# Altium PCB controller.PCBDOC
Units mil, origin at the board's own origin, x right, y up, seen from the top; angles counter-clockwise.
Board outline 3870 x 2950 mil, 2 copper layers (Top Layer, Bottom Layer); 33 components, 42 nets, 131 pads, 36 vias.
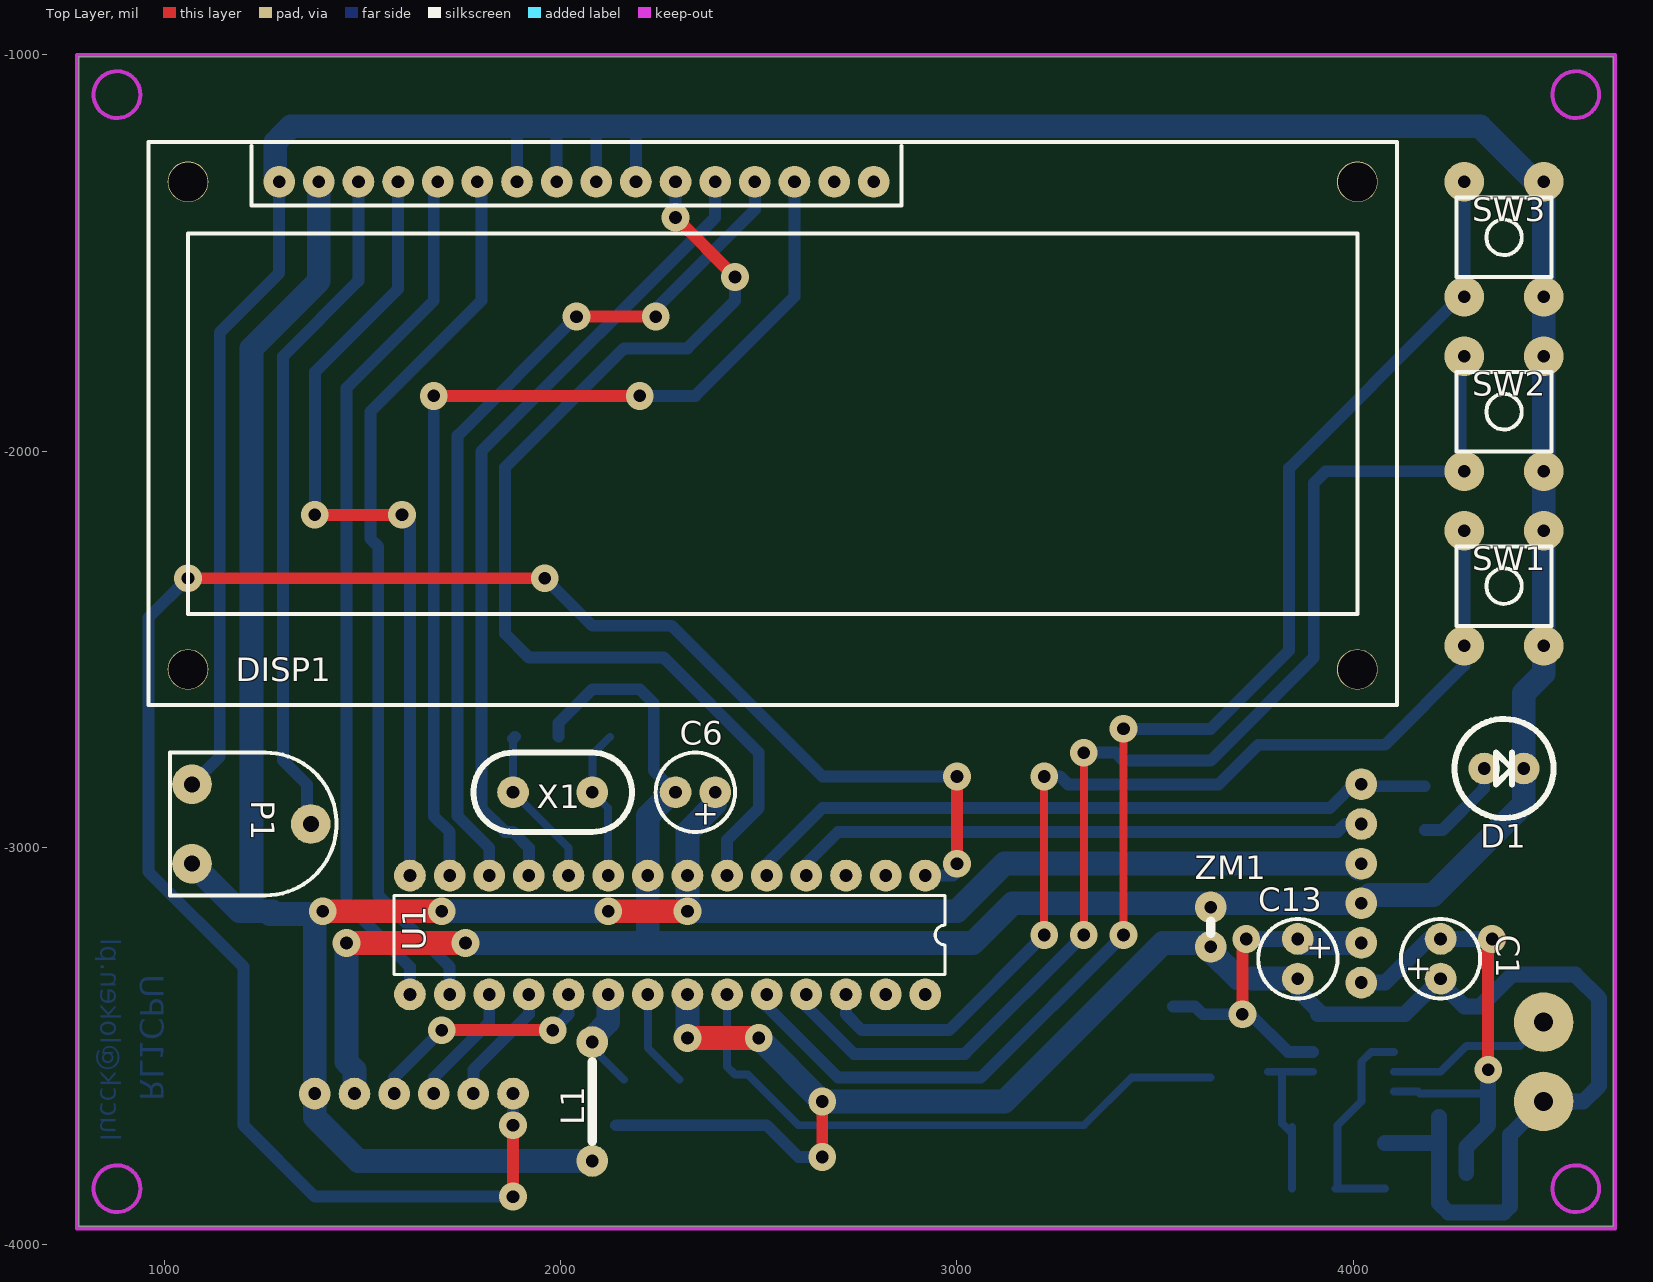
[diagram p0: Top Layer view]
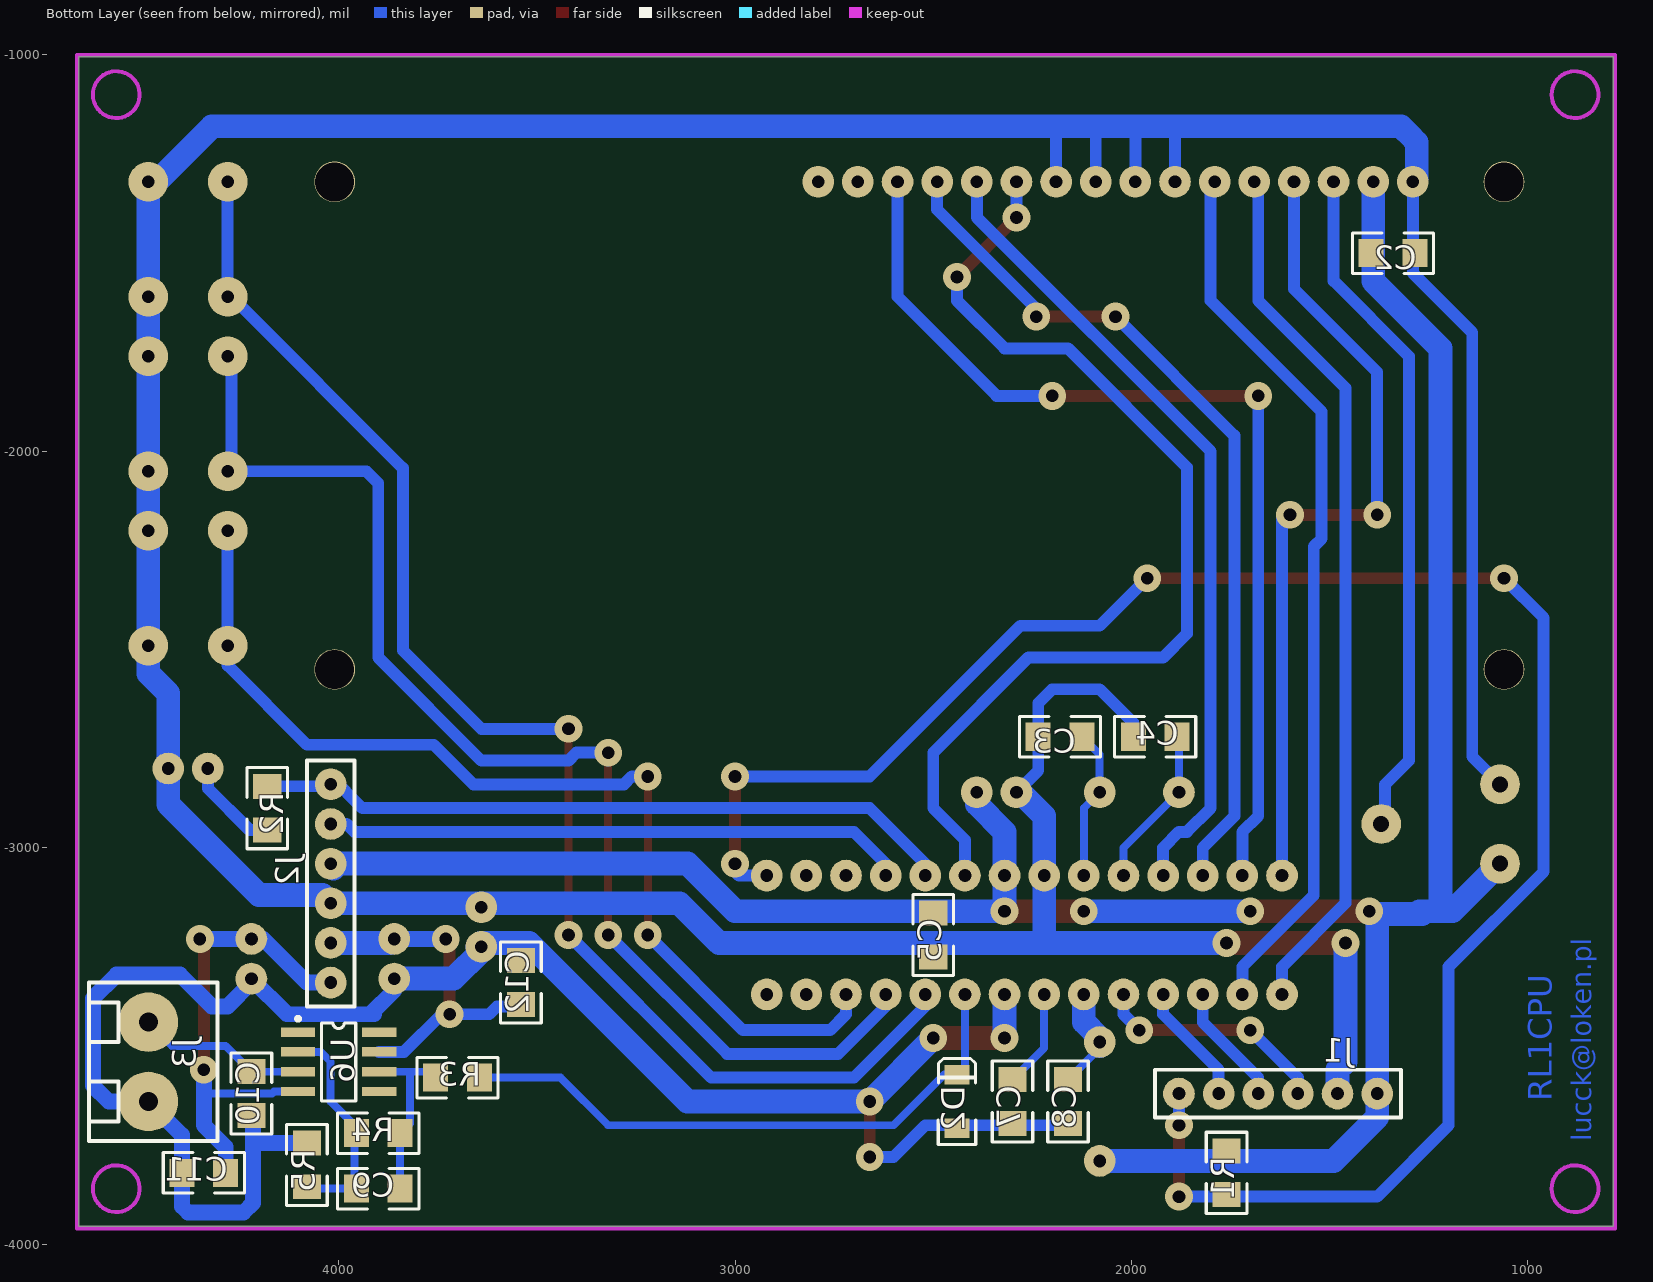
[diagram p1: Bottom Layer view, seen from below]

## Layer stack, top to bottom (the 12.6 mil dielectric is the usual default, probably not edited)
Top Layer: signal copper 1.4
Dielectric: dielectric 12.6, FR-4, Dk 4.8
Bottom Layer: signal copper 1.4

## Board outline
785,-3955 4655,-3955 4655,-1005 785,-1005

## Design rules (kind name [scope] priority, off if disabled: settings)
Clearance [All] p1: gap=12
ComponentClearance [All] p1: gap=12 collisioncheckmode=2
PolygonConnect [All] p1: connectstyle=Relief reliefconductorwidth=10 reliefentries=4 polygonreliefangle="90 Angle"
RoutingCorners [All] p1: cornerstyle=45-Degree minsetback=25 maxsetback=200
RoutingLayers [All] p1: top layer="Not Used" bottom layer=Any
RoutingVias [All] p1: holewidth=32 width=70 viastyle="Through Hole" minholewidth=32 minwidth=70 maxholewidth=32 maxwidth=100
SolderMaskExpansion [All] p1: expansion=4
TestPointUsage [All] p1: valid=0 allowmultiple=FALSE
Testpoint [All] p1: side=15 testpointundercomponent=TRUE minsize=40 maxsize=100 preferedsize=60 minholesize=0 maxholesize=40 preferedholesize=32 testpointgrid=1 style=1023 order=-539222988
Width [All] p1: maxlimit=200 minlimit=10 preferedwidth=20 toplayer_prefwidth=30 bottomlayer_prefwidth=30 minimp=50.000000 maximp=50.000000 favimp=50.000000
15 further rules are at their usual default settings.

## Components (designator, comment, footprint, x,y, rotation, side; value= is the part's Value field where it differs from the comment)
C1 "10u/16" CE5 4220,-3280 r90 top
C2 "100n" 1206 1340,-1500 r180 bottom
C3 "27p" 1206 2180,-2720 r0 bottom
C4 "27p" 1206 1940,-2720 r0 bottom
C5 "100n" 1206 2500,-3220 r270 bottom
C6 "10u/16" CE5 2340,-2860 r180 top
C7 "100n" 1206 2300,-3640 r270 bottom
C8 "100n" 1206 2160,-3640 r270 bottom
C9 "470n" 1206 3900,-3860 r180 bottom
C10 "100n" 1206 4220,-3620 r270 bottom
C11 "100n" 1206 4340,-3820 r180 bottom
C12 "100n" 1206 3540,-3340 r270 bottom
C13 "10u/16" CE5 3860,-3280 r270 top
D1 "Ziel" LED5 4380,-2800 r0 top
D2 "4V7" MMELF 2440,-3640 r90 bottom
DISP1 "LCD2X16" DTECH162A 960,-1220 r0 top
J1 "ISP" ZL6A 1380,-3620 r0 bottom
J2 "CPU" ZL6A 4020,-3340 r90 bottom
J3 "TERMO" ARK2 4480,-3540 r90 bottom
L1 "10u" R3 2080,-3640 r90 top
P1 "10k" PR3 1220,-2940 r270 top
R1 "22k" 1206 1760,-3820 r90 bottom
R2 "510" 1206 4180,-2900 r90 bottom
R3 "510" 1206 3700,-3580 r0 bottom
R4 "990k 1%" 1206 3900,-3720 r0 bottom
R5 "10k 1%" 1206 4080,-3800 r270 bottom
SW1 "SW-PB" DTS65P 4380,-2340 r270 top
SW2 "SW-PB" DTS65P 4380,-1900 r270 top
SW3 "SW-PB" DTS65P 4380,-1460 r270 top
U1 "ATMEGA8" U28L 2520,-3220 r180 top
U6 "OP07" SO-G8 4000,-3540 r270 bottom
X1 "8M" X2 1980,-2860 r180 top
ZM1 "0" R1 3640,-3200 r270 top

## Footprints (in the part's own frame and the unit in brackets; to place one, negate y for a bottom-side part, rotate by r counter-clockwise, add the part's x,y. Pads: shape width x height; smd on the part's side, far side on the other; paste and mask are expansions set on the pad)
1206 [mm]
  rect 1.6x1.8 smd: 1(-1.4,0) 2(1.4,0)
  silkscreen extent -2.6,-1.3 2.6,1.3
ARK2 [mil]
  round 150 hole 48: 1(-100,0) 2(100,0)
  silkscreen extent -200,-175 200,150
CE5 [mil]
  round 80 hole 32: 1(-50,0) 2(50,0)
  silkscreen extent -100,-100 100,100
DTECH162A [mil]
  round 102.36 hole 98.43: 0(100,-1330) 0(100,-100) 0(3050,-1330) 0(3050,-100)
  round 80 hole 32: 1(330,-100) 2(430,-100) 3(530,-100) 4(630,-100) 5(730,-100) 6(830,-100) 7(930,-100) 8(1030,-100) 9(1130,-100) 10(1230,-100) 11(1330,-100) 12(1430,-100) 13(1530,-100) 14(1630,-100) 15(1730,-100) 16(1830,-100)
  silkscreen extent 0,-1420 3150,0
DTS65P [mil]
  round 100 hole 32: 1(-140,100) 1(150,100) 2(-140,-100) 2(150,-100)
  silkscreen extent -100,-120 100,120
LED5 [mil]
  round 80 hole 32: 1(-50,0) 2(50,0)
  silkscreen extent -125,-125 125,125
MMELF [mm]
  rect 1.25x1.6 smd: 1(-1.725,0) 2(1.725,0)
  silkscreen extent -2.75,-1.2 2.76,1.2
PR3 [mil]
  round 100 hole 40: 1(-100,-150) 2(0,150) 3(100,-150)
  silkscreen extent -180,-205 180,215
R1 [mil]
  round 80 hole 32: 1(-50,0) 2(50,0)
  silkscreen extent -15,0 15,0
R3 [mil]
  round 80 hole 32: 1(-150,0) 2(150,0)
  silkscreen extent -100,0 100,0
SO-G8 [mm]
  rect 0.6x2.2 smd: 1(-1.905,-2.6) 2(-0.635,-2.6) 3(0.635,-2.6) 4(1.905,-2.6) 5(1.905,2.6) 6(0.635,2.6) 7(-0.635,2.6) 8(-1.905,2.6)
  silkscreen extent -2.88,-2.72 2.5,1.1
U28L [mil]
  round 80 hole 32: 1(-400,-150) 2(-300,-150) 3(-200,-150) 4(-100,-150) 5(0,-150) 6(100,-150) 7(200,-150) 8(300,-150) 9(400,-150) 10(500,-150) 11(600,-150) 12(700,-150) 13(800,-150) 14(900,-150) 15(900,150) 16(800,150) 17(700,150) 18(600,150) 19(500,150) 20(400,150) 21(300,150) 22(200,150) 23(100,150) 24(0,150) 25(-100,150) 26(-200,150) 27(-300,150) 28(-400,150)
  silkscreen extent -450,-100 940,100
X2 [mil]
  round 80 hole 32: 1(100,0) 2(-100,0)
  silkscreen extent -200,-100 200,100
ZL6A [mil]
  round 80 hole 32: 1(0,0) 2(100,0) 3(200,0) 4(300,0) 5(400,0) 6(500,0)
  silkscreen extent -60,-60 560,60

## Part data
C1 C6 C13: library part EL, "Elektrolit"
C2 C3 C4 C5 C7 C8 C9 C10 C11 C12: library part C, "Kondensator"
D1: library part LED, "Dioda LED"
D2: library part DZ, "Dioda Zenera"
DISP1: "Wyswietlacz LCD 2x16"
J1 J2: library part CON6, "Z彻cze 6"
J3: library part CON2, "Z彻cze ARK2"
L1: library part L, "Cewka"
P1: library part POT, "Potencjometr"
R1 R2 R3 R4 R5 ZM1: library part R, "Rezystor"
SW1 SW2 SW3: "Mikroswitch"
U1: library part ATMEGA8_DIP28, "Atmel Microcontroller - Library created by carel..  <www.mpfreezone.com>"
U6: "Ultra-Low Offset Voltage Operational Amplifier"
X1: library part XTAL, "Crystal"

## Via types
v1: diameter 70, hole 32, Top Layer to Bottom Layer, 36 vias

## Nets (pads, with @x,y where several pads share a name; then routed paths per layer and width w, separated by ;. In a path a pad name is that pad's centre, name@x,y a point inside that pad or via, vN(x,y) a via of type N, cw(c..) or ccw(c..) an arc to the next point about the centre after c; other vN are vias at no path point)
GND: C2.2 C3.2 C4.2 C5.2 C6.2 D1.2 DISP1.1 DISP1.7 DISP1.8 DISP1.9 DISP1.10 J1.2 J2.3 P1.1 SW1.1 SW2.1 SW3.1 U1.8 ZM1.1 | length 11535.2
  Top Layer w60: v1(1460,-3240) v1(1760,-3240)
  Bottom Layer w30: P1.1 1140,-2770 1140,-1700 1290,-1550 DISP1.1 ; DISP1.7 1890,-1190 ; DISP1.8 1990,-1210 ; C4.2 1995.12,-2684.88 2080,-2600 2200,-2600 2235.12,-2635.12 2235.12,-2805.12 C6.2 ; DISP1.9 2090,-1190 ; DISP1.10 2190,-1190
  Bottom Layer w60: 1280,-1220 1280,-1310 DISP1.1 ; 1290,-1210 1320,-1180 4320,-1180 4480,-1340 4480,-1620 4480,-2050 4480,-2200 4480,-2560 4430,-2610 4430,-2890 4200.64,-3119.36 4040.64,-3119.36 J2.3 3140,-3140 3040,-3240 v1(1760,-3240) ; v1(1460,-3240) 1460,-3540 1480,-3560 J1.2 ; 2220,-3240 2220,-2920 C6.2@2280,-2860
GNDA: C1.1 C7.2 C8.2 C10.2 C11.1 C12.1 C13.2 D2.1 J3.1 R5.1 U1.22 ZM1.2 | length 4828.4
  Top Layer w30: v1(2660,-3780) v1(2660,-3640)
  Top Layer w60: v1(2320,-3480) v1(2500,-3480)
  Bottom Layer w20: C10.2@4215.78,-3679.33 C10.2 ; 4395.12,-3875.12 4400,-3880
  Bottom Layer w30: C8.2@2140,-3700 2520,-3700 2600,-3780 v1(2660,-3780)
  Bottom Layer w40: C13.2 3860,-3360 3920,-3420 ; 3910,-3420 4120,-3420 ; R5.1 4210.9,-3744.88 4215.78,-3740 ; 4130,-3420 C1.1 4220,-3340 4280,-3400 4320,-3400 4400,-3320 4560,-3320 4620,-3380 4620,-3600 4580,-3640 J3.1@4460,-3640 ; C10.2@4215.78,-3679.33 4215.78,-3895.78 4240,-3920 4380,-3920 4395.12,-3904.88 4395.12,-3875.12 4395.12,-3724.88 J3.1
  Bottom Layer w60: v1(2320,-3480) U1.22 ; v1(2500,-3480) v1(2660,-3640) 3120,-3640 3520,-3240 ZM1.2@3640,-3240 ; ZM1.2@3650,-3250 ZM1.2 3640,-3260 3710,-3330 C13.2
GRZ: J2.6 R2.2 U1.5 | length 1818.4
  Bottom Layer w20: U1.5 U1.5@2530,-3070 ; J2.6@3994.75,-2840 J2.6
  Bottom Layer w30: U1.5 2520,-3040 2660,-2900 3940,-2900 J2.6@4020,-2820 ; J2.6 4024.88,-2844.88 R2.2
M9V: C1.2 C11.2 J2.1 U6.4 | length 1246.4
  Top Layer w30: v1(4340,-3560) 4340,-3240 v1(4350,-3230)
  Bottom Layer w20: U6.4 4162.57,-3615 4167.57,-3620 4340,-3620
  Bottom Layer w40: J2.1 4080,-3340 4190,-3230 v1(4350,-3230) ; C1.2 C1.2@4230,-3240 ; C11.2 4284.88,-3755.12 4340,-3700 v1(4340,-3560)
MISO: J1.5 U1.18 | length 308
  Bottom Layer w30: J1.5 1780,-3560 1920,-3420 U1.18
MOSI: J1.4 U1.17 | length 308
  Bottom Layer w30: J1.4 1680,-3580 1820,-3440 U1.17
NetC1_1: 
NetC2_1: 
NetC3_1: C3.1 U1.9 X1.2 | length 385.2
  Bottom Layer w20: U1.9 2120,-2900 X1.2 2080,-2764.88 C3.1
NetC4_1: C4.1 U1.10 X1.1 | length 410
  Bottom Layer w20: C4.1@1880,-2724.88 X1.1 2020,-3000 U1.10
  Bottom Layer w30: C4.1@1880,-2724.88 C4.1
NetC7_1: C7.1 U1.21 | length 248
  Bottom Layer w20: U1.21 2220,-3504.88 C7.1
NetC8_1: C8.1 L1.2 U1.20 | length 274.6
  Bottom Layer w20: L1.2 2080,-3504.88 C8.1
  Bottom Layer w60: L1.2@2080,-3500 2080,-3480 2120,-3440 U1.20
NetC9_1: C9.1 R4.2 R5.2 U6.2 | length 562.5
  Bottom Layer w20: C9.1 R5.2@4080,-3860 ; C9.1@3960,-3860 3960,-3720 3960,-3700 4020,-3640 4020,-3540 4045,-3515 U6.2
NetC9_2: C9.2 R3.2 R4.1 U6.6 | length 433.1
  Bottom Layer w20: R3.2@3785,-3565 U6.6 ; 3820,-3565 3820,-3695.12 R4.1 ; C9.2 R4.1@3844.88,-3704.88
NetC10_1: C10.1 J3.2 U6.3 | length 429.4
  Bottom Layer w20: U6.3 4219.88,-3565 4284.88,-3500 4420,-3500 J3.2
NetD1_1: D1.1 R2.1 | length 243.5
  Bottom Layer w30: R2.1 4224.88,-2955.12 4330,-2850 D1.1
NetD1_2: 
NetD2_2: D2.2 R3.1 U1.23 | length 1513.1
  Bottom Layer w20: U1.23 2420,-3552.09 D2.2 2472.09,-3572.09 2600,-3700 3320,-3700 3440,-3580 R3.1@3640,-3580
NetD3_2: 
NetDISP1_3: DISP1.3 P1.2 | length 1723.6
  Bottom Layer w30: P1.2@1360,-2940 1360,-2840 1300,-2780 1300,-1760 1490,-1570 DISP1.3
NetDISP1_4: DISP1.4 U1.14 | length 2077
  Top Layer w30: v1(1380,-2160) v1(1600,-2160)
  Bottom Layer w30: v1(1380,-2160) 1380,-1800 1590,-1590 DISP1.4 ; v1(1600,-2160) 1620,-2160 U1.14
NetDISP1_5: DISP1.5 U1.15 | length 2221.5
  Bottom Layer w30: U1.15@1620,-3380 1620,-3300 1460,-3140 1460,-1840 1680,-1620 1680,-1330 DISP1.5
NetDISP1_6: DISP1.6 U1.16 | length 2248.8
  Bottom Layer w30: U1.16 1720,-3300 1540,-3120 1540,-2240 1520,-2220 1520,-1900 1800,-1620 DISP1.6@1800,-1320
NetDISP1_11: DISP1.11 U1.6 | length 2643.5
  Top Layer w30: v1(2290,-1410) v1(2440,-1560)
  Bottom Layer w30: v1(2290,-1410) DISP1.11 ; U1.6 2420,-2980 2500,-2900 2500,-2760 2260,-2520 1920,-2520 1860,-2460 1860,-2040 2160,-1740 2320,-1740 2440,-1620 v1(2440,-1560)
NetDISP1_12: DISP1.12 U1.11 | length 2055.8
  Bottom Layer w30: U1.11 1920,-3000 1880,-2960 1860,-2960 1800,-2900 1800,-2000 2390,-1410 DISP1.12
NetDISP1_13: DISP1.13 U1.12 | length 2211
  Top Layer w30: v1(2040,-1660) v1(2240,-1660)
  Bottom Layer w30: U1.12 1820,-3000 1740,-2920 1740,-1960 v1(2040,-1660) ; v1(2240,-1660) 2240,-1640 2490,-1390 DISP1.13
NetDISP1_14: DISP1.14 U1.13 | length 2534.3
  Top Layer w30: v1(1680,-1860) v1(2200,-1860)
  Bottom Layer w30: v1(1680,-1860) 1680,-2920 1720,-2960 U1.13 ; v1(2200,-1860) 2340,-1860 2590,-1610 2590,-1330 DISP1.14@2580,-1320
NetJ1_1: 
NetJ1_3: 
NetJ2_2: 
NetQ1_1: 
NetQ1_4: 
NetQ1_6: 
NetR5_1: 
NetSW1_2: SW1.2 U1.26 | length 2618.5
  Top Layer w20: v1(3220,-3220) v1(3220,-2820)
  Bottom Layer w30: U1.26 2720,-3420 2760,-3460 2980,-3460 v1(3220,-3220) ; v1(3220,-2820) 3260,-2820 3280,-2840 3660,-2840 3760,-2740 4080,-2740 4280,-2540 SW1.2@4280,-2180
NetSW2_2: SW2.2 U1.25 | length 3210.7
  Top Layer w20: v1(3320,-3220) v1(3320,-2760)
  Bottom Layer w30: U1.25 2620,-3400 2740,-3520 3020,-3520 v1(3320,-3220) ; v1@3300,-2760 v1@3320,-2780 ; v1(3320,-2760) 3400,-2760 3420,-2780 3640,-2780 3900,-2520 3900,-2080 3930,-2050 4270,-2050 SW2.2@4270,-1750
NetSW3_2: SW3.2 U1.24 | length 3548.8
  Top Layer w20: v1(3420,-3220) v1(3420,-2700)
  Bottom Layer w30: U1.24 2520,-3400 2700,-3580 3060,-3580 v1(3420,-3220) ; v1(3420,-2700) 3640,-2700 3838,-2502 3838,-2042 SW3.2@4260,-1620 ; SW3.2@4280,-1610 4280,-1320 SW3.2@4300,-1300
P9V: C12.2 C13.1 J2.2 U6.7 | length 888.7
  Top Layer w30: v1(3720,-3420) 3720,-3240 v1(3730,-3230)
  Bottom Layer w30: C12.2@3544.88,-3400 3600,-3400 3620,-3420 3740,-3420 3835,-3515 U6.7
  Bottom Layer w40: v1(3730,-3230) C13.1
  Bottom Layer w60: C13.1 3870,-3240 J2.2
RST: J1.6 R1.1 U1.1 | length 4986.6
  Top Layer w30: v1(1060,-2320) v1(1960,-2320) ; v1(1880,-3880) v1(1880,-3700) ; v1@3000,-3020 v1(3000,-2820)
  Bottom Layer w30: v1(1060,-2320) 960,-2420 960,-3060 1200,-3300 1200,-3700 1380,-3880 v1(1880,-3880) ; v1(1880,-3700) J1.6 ; v1(1960,-2320) 2080,-2440 2280,-2440 2660,-2820 v1(3000,-2820) ; U1.1 2990,-3070 3000,-3060 v1(3000,-3040)
SCK: J1.3 U1.19 | length 596.3
  Top Layer w30: v1(1700,-3460) v1(1980,-3460)
  Bottom Layer w30: J1.3 1580,-3580 v1(1700,-3460) ; v1(1980,-3460) 2020,-3420 U1.19
VCC: C2.1 C5.1 C6.1 DISP1.2 J1.1 J2.4 L1.1 P1.3 R1.2 U1.7 | length 6570.1
  Top Layer w60: v1(1400,-3160) v1(1700,-3160) ; v1(2120,-3160) v1(2320,-3160)
  Bottom Layer w60: P1.3 1190,-3160 1273.19,-3160 1280,-3166.81 ; 1220,-3160 1220,-1740 1390,-1570 DISP1.2 ; 1266.81,-3166.81 v1@1393.19,-3166.81 ; v1(1400,-3160) 1380,-3180 1380,-3680 1490,-3790 L1.1 ; v1(1700,-3160) v1(2120,-3160) ; C6.1 2390,-2890 2320,-2960 v1(2320,-3160) 3000,-3160 3120,-3040 4000,-3040 J2.4@4012.91,-3052.91
ZCD: J2.5 U1.4 | length 1491.4
  Bottom Layer w20: U1.4 U1.4@2620,-3040 ; J2.5 J2.5@4020,-2920
  Bottom Layer w30: U1.4@2620,-3040 2700,-2960 3960,-2960 3980,-2940 J2.5
pads on no net: DISP1.0 DISP1.15 DISP1.16 U1.2 U1.3 U1.27 U1.28 U6.1 U6.5 U6.8

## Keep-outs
Keep-Out Layer:
  circle w10: c880.94,-1100 r59.06
  circle w10: c4560.94,-1100 r59.06
  circle w10: c4560.94,-3860 r59.06
  circle w10: c880.94,-3860 r59.06
  lines w10: 780,-3960 780,-1000 4660,-1000 4660,-3960 780,-3960

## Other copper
Bottom Layer:
  text "RL1CPU" at 940,-3640 h60 r270
  text "lucck@loken.pl" at 840,-3740 h50 r270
